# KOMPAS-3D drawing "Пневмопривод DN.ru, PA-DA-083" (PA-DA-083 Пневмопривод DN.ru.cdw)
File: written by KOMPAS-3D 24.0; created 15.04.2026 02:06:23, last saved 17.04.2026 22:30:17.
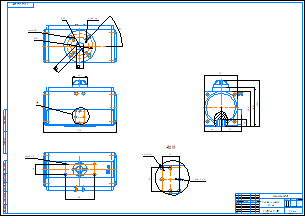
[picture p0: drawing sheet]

Document properties: Автор: DN.ru; Форматы листов документа: A1; Полное имя файла: PA-DA-083 Пневмопривод DN.ru.m3d; Масса: 3.1; Наименование: Пневмопривод DN.ru; Количество листов документа: 1; Примечание: D290-00295

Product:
- Part/product: Пневмопривод DN.ru  | designation PA-DA-083
    Масса: 3.1
    Раздел спецификации: Прочие изделия
    Примечание: D290-00295

Views: Вид 1, Вид:1, Проекционный вид 2, Выносной элемент 6, Выносной элемент А, Выносной элемент
Referenced files in C:\Работа\PA-DA-х Пневмопривод DN.ru\052\: PA-DA-052 Пневмопривод DN.ru.m3d
Referenced files in C:\Работа\PA-DA-х Пневмопривод DN.ru\083\: PA-DA-083 Пневмопривод DN.ru.m3d
Referenced files in C:\Program Files\ASCON\KOMPAS-3D v24\Templates\: Чертеж_DN.ru.cdt
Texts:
  objid
  viewid
  PA-DA-083
  Чертеж_DN.ru.cdt
  Пневмопривод
  Пневмопривод DN.ru
  PA-DA-083 Пневмопривод DN.ru
Dimensions and other numbers on the sheet: 0; 3; 2; 4; 40; 608; 204; 4 отв.; 6; 17; 50; 70; 8; 7; 1; 2 отв.; 24; 32; 5; 1:1; 3,1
